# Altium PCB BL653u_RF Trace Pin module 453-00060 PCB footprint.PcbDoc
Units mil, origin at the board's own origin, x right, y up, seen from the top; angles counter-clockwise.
Board outline 220.47 x 248.03 mil, 2 copper layers (Top Layer, Bottom Layer); 1 components, 0 nets, 53 pads, 0 vias.
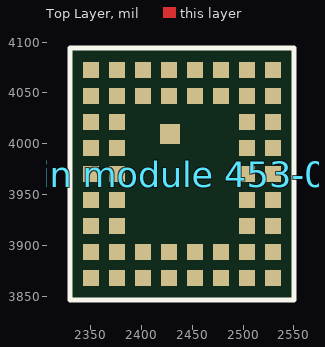
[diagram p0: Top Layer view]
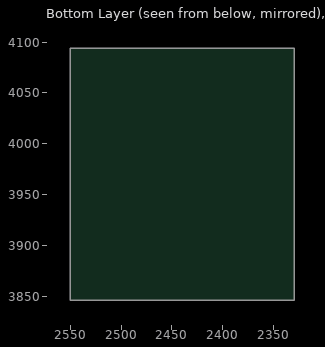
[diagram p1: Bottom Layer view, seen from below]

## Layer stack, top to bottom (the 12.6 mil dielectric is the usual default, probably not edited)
Top Solder: solder mask 0.4, Solder Resist, Dk 3.5
Top Layer: signal copper 1.4
Dielectric 1: dielectric 12.6, FR-4, Dk 4.8
Bottom Layer: signal copper 1.4
Bottom Solder: solder mask 0.4, Solder Resist, Dk 3.5

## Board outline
2329.76,3845.98 2550.24,3845.98 2550.24,4094.02 2329.76,4094.02

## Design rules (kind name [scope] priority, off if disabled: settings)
Clearance [All] p1: gap=10 ignorepadtopadclearanceinfootprint=FALSE except(0: Arc-Hole Track-Hole SMDPad-Hole THPad-Hole Via-Hole Fill-Hole Poly-Hole Region-Hole Text-Hole)
PolygonConnect [All] p1: connectstyle=Relief reliefconductorwidth=10 reliefentries=4 polygonreliefangle="90 Angle" airgapwidth=10
RoutingVias [All] p1: holewidth=28 width=50 viastyle="Through Hole" minholewidth=28 minwidth=50 maxholewidth=28 maxwidth=50
SolderMaskExpansion [All] p1: expansion=4
Width [All] p1: maxlimit=10 minlimit=10 preferedwidth=10
30 further rules are at their usual default settings.

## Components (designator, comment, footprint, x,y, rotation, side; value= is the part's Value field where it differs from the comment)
"BL653u_RF Trace Pin module 453-00060 PCB footprint" "Comment" "LAIRD, BL653U_ST_MODULE" 2440,3970 r0 top

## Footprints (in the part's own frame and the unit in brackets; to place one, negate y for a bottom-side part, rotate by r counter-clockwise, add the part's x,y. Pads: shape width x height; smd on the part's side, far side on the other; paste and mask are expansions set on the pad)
"LAIRD, BL653U_ST_MODULE" [mm] "Laird, BL653 Module"
  rect 0.4x0.4 smd mask+0.051: 1(2.275,2.6) 2(2.275,1.95) 3(2.275,1.3) 4(2.275,0.65) 5(2.275,0) 6(2.275,-0.65) 7(2.275,-1.3) 8(2.275,-1.95) 9(2.275,-2.6) 10(1.625,-2.6) 11(0.975,-2.6) 12(0.325,-2.6) 13(-0.325,-2.6) 14(-0.975,-2.6) 15(-1.625,-2.6) 16(-2.275,-2.6) 17(-2.275,-1.95) 18(-2.275,-1.3) 19(-2.275,-0.65) 20(-2.275,0) 21(-2.275,0.65) 22(-2.275,1.3) 23(-2.275,1.95) 24(-2.275,2.6) 25(-1.625,2.6) 26(-0.975,2.6) 27(-0.325,2.6) 28(0.325,2.6) 29(0.975,2.6) 30(1.625,2.6) 31(1.625,1.95) 32(1.625,1.3) 33(1.625,0.65) 34(1.625,0) 35(1.625,-0.65) 36(1.625,-1.3) 37(1.625,-1.95) 38(0.975,-1.95) 39(0.325,-1.95) 40(-0.325,-1.95) 41(-0.975,-1.95) 42(-1.625,-1.95) 43(-1.625,-1.3) 44(-1.625,-0.65) 45(-1.625,0) 46(-1.625,0.65) 47(-1.625,1.3) 48(-1.625,1.95) 49(-0.975,1.95) 50(-0.325,1.95) 51(0.325,1.95) 52(0.975,1.95)
  rect 0.5x0.5 smd mask+0.051: G1(-0.3,1)
  silkscreen extent -2.8,-3.15 2.8,3.15, body extent -2.47,-2.8 2.47,2.8, height 0.01

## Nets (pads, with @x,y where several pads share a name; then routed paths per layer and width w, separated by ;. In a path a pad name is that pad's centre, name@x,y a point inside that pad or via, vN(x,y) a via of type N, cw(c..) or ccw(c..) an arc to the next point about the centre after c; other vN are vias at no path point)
pads on no net: "BL653u_RF Trace Pin module 453-00060 PCB footprint.1" "BL653u_RF Trace Pin module 453-00060 PCB footprint.2" "BL653u_RF Trace Pin module 453-00060 PCB footprint.3" "BL653u_RF Trace Pin module 453-00060 PCB footprint.4" "BL653u_RF Trace Pin module 453-00060 PCB footprint.5" "BL653u_RF Trace Pin module 453-00060 PCB footprint.6" "BL653u_RF Trace Pin module 453-00060 PCB footprint.7" "BL653u_RF Trace Pin module 453-00060 PCB footprint.8" "BL653u_RF Trace Pin module 453-00060 PCB footprint.9" "BL653u_RF Trace Pin module 453-00060 PCB footprint.10" "BL653u_RF Trace Pin module 453-00060 PCB footprint.11" "BL653u_RF Trace Pin module 453-00060 PCB footprint.12" "BL653u_RF Trace Pin module 453-00060 PCB footprint.13" "BL653u_RF Trace Pin module 453-00060 PCB footprint.14" "BL653u_RF Trace Pin module 453-00060 PCB footprint.15" "BL653u_RF Trace Pin module 453-00060 PCB footprint.16" "BL653u_RF Trace Pin module 453-00060 PCB footprint.17" "BL653u_RF Trace Pin module 453-00060 PCB footprint.18" "BL653u_RF Trace Pin module 453-00060 PCB footprint.19" "BL653u_RF Trace Pin module 453-00060 PCB footprint.20" "BL653u_RF Trace Pin module 453-00060 PCB footprint.21" "BL653u_RF Trace Pin module 453-00060 PCB footprint.22" "BL653u_RF Trace Pin module 453-00060 PCB footprint.23" "BL653u_RF Trace Pin module 453-00060 PCB footprint.24" "BL653u_RF Trace Pin module 453-00060 PCB footprint.25" "BL653u_RF Trace Pin module 453-00060 PCB footprint.26" "BL653u_RF Trace Pin module 453-00060 PCB footprint.27" "BL653u_RF Trace Pin module 453-00060 PCB footprint.28" "BL653u_RF Trace Pin module 453-00060 PCB footprint.29" "BL653u_RF Trace Pin module 453-00060 PCB footprint.30" "BL653u_RF Trace Pin module 453-00060 PCB footprint.31" "BL653u_RF Trace Pin module 453-00060 PCB footprint.32" "BL653u_RF Trace Pin module 453-00060 PCB footprint.33" "BL653u_RF Trace Pin module 453-00060 PCB footprint.34" "BL653u_RF Trace Pin module 453-00060 PCB footprint.35" "BL653u_RF Trace Pin module 453-00060 PCB footprint.36" "BL653u_RF Trace Pin module 453-00060 PCB footprint.37" "BL653u_RF Trace Pin module 453-00060 PCB footprint.38" "BL653u_RF Trace Pin module 453-00060 PCB footprint.39" "BL653u_RF Trace Pin module 453-00060 PCB footprint.40" "BL653u_RF Trace Pin module 453-00060 PCB footprint.41" "BL653u_RF Trace Pin module 453-00060 PCB footprint.42" "BL653u_RF Trace Pin module 453-00060 PCB footprint.43" "BL653u_RF Trace Pin module 453-00060 PCB footprint.44" "BL653u_RF Trace Pin module 453-00060 PCB footprint.45" "BL653u_RF Trace Pin module 453-00060 PCB footprint.46" "BL653u_RF Trace Pin module 453-00060 PCB footprint.47" "BL653u_RF Trace Pin module 453-00060 PCB footprint.48" "BL653u_RF Trace Pin module 453-00060 PCB footprint.49" "BL653u_RF Trace Pin module 453-00060 PCB footprint.50" "BL653u_RF Trace Pin module 453-00060 PCB footprint.51" "BL653u_RF Trace Pin module 453-00060 PCB footprint.52" "BL653u_RF Trace Pin module 453-00060 PCB footprint.G1"

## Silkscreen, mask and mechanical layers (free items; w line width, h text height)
Mechanical 1:
  the board outline again, w0.98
